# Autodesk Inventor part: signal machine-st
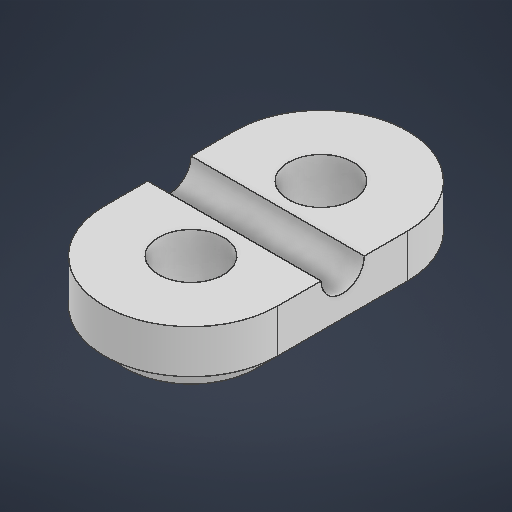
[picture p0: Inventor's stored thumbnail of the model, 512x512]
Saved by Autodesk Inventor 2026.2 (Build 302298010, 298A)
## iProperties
Created: 2026-05
Part Number: signal machine-st
Material: 일반
Document SubType Name: Modeling
Designer: work
Density: 1 g/cm^3
Appearance: 기본값
Author: work
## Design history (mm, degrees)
sketch "스케치1"
  geometry: L1 (0, 0)-(0, -6); L2 (0, 0)-(0, -6); L3 (-4, 0)-(-4, -6); L4 (4, -6)-(4, 0); C1 r 1.5 at (0, 0); C2 r 1.5 at (0, -6); A1 r 4 centre (0, 0) between (4, 0) and (-4, 0); A2 r 4 centre (0, -6) between (-4, -6) and (4, -6); 1 further point
  constraints: 10 end point, 4 centre point, 4 point on circle, 4 tangent, 2 coincident, 2 equal length, 2 midpoint, 1 vertical
  dimensions: "d0" = 6 distance of L1.start L1.end; "d1" = 3 diameter of C1; "d2" = 3 diameter of C2; "d3" = 4 radius of A2
extrude "돌출1" new body sketch "스케치1" distance "d4" = 3; taper "d5" = 0 deg
sketch "스케치2"
  geometry: L1 (6, 3)-(0, 3) reference; C1 r 1 at (3, 3); 3 further points
  constraints: 1 centre point, 1 midpoint
  dimensions: "d6" = 2 diameter of C1
extrude "돌출2" cut sketch "스케치2" extent not by distance; stored distance "d7" = 0; taper "d8" = 0 deg
chamfer "모따기1" distance "d9" = 1; stored, may be unused: second distance "d10" = 2, angle "d11" = 45 deg
node "솔리드1"
